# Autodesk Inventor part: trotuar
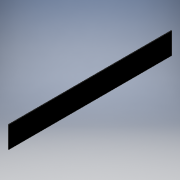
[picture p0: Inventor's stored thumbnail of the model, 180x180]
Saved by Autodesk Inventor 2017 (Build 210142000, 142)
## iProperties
Created: 2017-11
Part Number: trotuar
Material: Generic
Document SubType Name: Modeling
Designer: iusti
Density: 1 g/cm^3
Appearance: Default
Author: iusti
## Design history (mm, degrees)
sketch "Sketch1"
  geometry: L1 (7500, 1000)-(-7500, 1000); L2 (-7500, 1000)-(-7500, -1000); L3 (-7500, -1000)-(7500, -1000); L4 (7500, -1000)-(7500, 1000); L5 (7500, 1000)-(-7500, -1000); L6 (-7500, 1000)-(7500, -1000); 1 further point
  constraints: 12 end point, 2 midpoint, 2 parallel, 1 horizontal, 1 perpendicular
  dimensions: "d0" = 2000 distance of L3.end L1.start; "d1" = 15000 distance of L1.start L1.end
extrude "Extrusion1" new body sketch "Sketch1" distance "d2" = 50; taper "d3" = 0 deg
body "Solid1"
